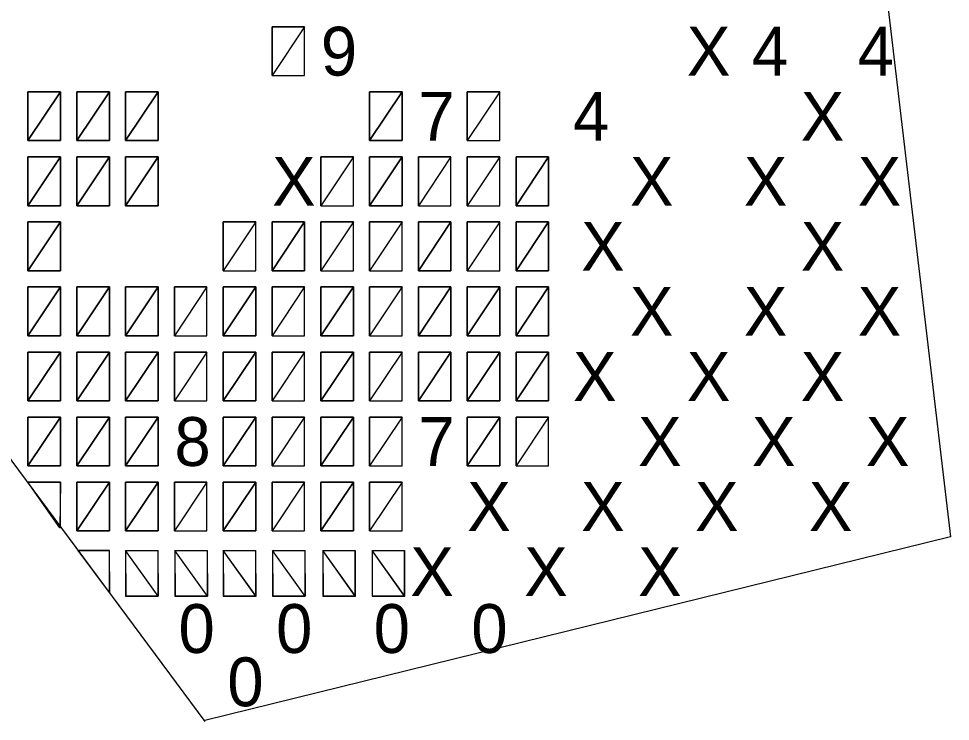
# Model space of a CAD drawing. Extents: x 0 to 44.3, y 0 to 22.
# Drawn here: x 4.6543 to 4.8173, y 1.2385 to 1.3615 of the extents above; entities that cross this region are included whole.
import ezdxf

# ---------------------------------------------------------------- set-up
doc = ezdxf.new("R2010")
doc.units = 0
doc.layers.add('Default', color=7, linetype='Continuous')

msp = doc.modelspace()

# ---------------------------------------------------------------- linework, layer by layer
at = {"layer": 'Default'}
for p, q in [((4.78805, 1.51939), (4.81727, 1.27081)), ((4.70432, 1.36004), (4.69863, 1.36004)), ((4.69863, 1.36004), (4.69863, 1.3515)), ((4.70432, 1.3515), (4.70432, 1.36004)), ((4.69863, 1.3515), (4.70432, 1.3515)), ((4.65595, 1.34866), (4.65595, 1.34012)), ((4.66164, 1.34866), (4.65595, 1.34866)), ((4.66164, 1.34012), (4.66164, 1.34866)), ((4.67018, 1.34866), (4.66449, 1.34866)), ((4.66449, 1.34866), (4.66449, 1.34012)), ((4.67018, 1.34012), (4.67018, 1.34866)), ((4.67302, 1.34866), (4.67302, 1.34012)), ((4.67871, 1.34866), (4.67302, 1.34866)), ((4.67871, 1.34012), (4.67871, 1.34866)), ((4.72139, 1.34866), (4.7157, 1.34866)), ((4.7157, 1.34866), (4.7157, 1.34012)), ((4.72139, 1.34012), (4.72139, 1.34866)), ((4.73277, 1.34866), (4.73277, 1.34012)), ((4.73846, 1.34866), (4.73277, 1.34866)), ((4.73846, 1.34012), (4.73846, 1.34866)), ((4.6068, 1.34644), (4.68687, 1.23853)), ((4.65595, 1.34012), (4.66164, 1.34012)), ((4.66449, 1.34012), (4.67018, 1.34012)), ((4.67302, 1.34012), (4.67871, 1.34012)), ((4.7157, 1.34012), (4.72139, 1.34012)), ((4.73277, 1.34012), (4.73846, 1.34012)), ((4.65595, 1.33728), (4.65595, 1.32874)), ((4.66164, 1.33728), (4.65595, 1.33728)), ((4.66164, 1.32874), (4.66164, 1.33728)), ((4.66449, 1.33728), (4.66449, 1.32874)), ((4.67018, 1.33728), (4.66449, 1.33728)), ((4.67018, 1.32874), (4.67018, 1.33728)), ((4.67871, 1.33728), (4.67302, 1.33728)), ((4.67302, 1.33728), (4.67302, 1.32874)), ((4.67871, 1.32874), (4.67871, 1.33728)), ((4.70717, 1.33728), (4.70717, 1.32874)), ((4.71286, 1.33728), (4.70717, 1.33728)), ((4.71286, 1.32874), (4.71286, 1.33728)), ((4.7157, 1.33728), (4.7157, 1.32874)), ((4.72139, 1.33728), (4.7157, 1.33728)), ((4.72139, 1.32874), (4.72139, 1.33728)), ((4.72993, 1.33728), (4.72424, 1.33728)), ((4.72424, 1.33728), (4.72424, 1.32874)), ((4.72993, 1.32874), (4.72993, 1.33728)), ((4.73846, 1.33728), (4.73277, 1.33728)), ((4.73277, 1.33728), (4.73277, 1.32874)), ((4.73846, 1.32874), (4.73846, 1.33728)), ((4.74131, 1.33728), (4.74131, 1.32874)), ((4.747, 1.33728), (4.74131, 1.33728)), ((4.747, 1.32874), (4.747, 1.33728)), ((4.65595, 1.32874), (4.66164, 1.32874)), ((4.66449, 1.32874), (4.67018, 1.32874)), ((4.67302, 1.32874), (4.67871, 1.32874)), ((4.70717, 1.32874), (4.71286, 1.32874)), ((4.7157, 1.32874), (4.72139, 1.32874)), ((4.72424, 1.32874), (4.72993, 1.32874)), ((4.73277, 1.32874), (4.73846, 1.32874)), ((4.74131, 1.32874), (4.747, 1.32874)), ((4.66164, 1.3259), (4.65595, 1.3259)), ((4.65595, 1.3259), (4.65595, 1.31736)), ((4.66164, 1.31736), (4.66164, 1.3259)), ((4.69578, 1.3259), (4.69009, 1.3259)), ((4.69009, 1.3259), (4.69009, 1.31736)), ((4.69578, 1.31736), (4.69578, 1.3259)), ((4.70432, 1.3259), (4.69863, 1.3259)), ((4.69863, 1.3259), (4.69863, 1.31736)), ((4.70432, 1.31736), (4.70432, 1.3259)), ((4.70717, 1.3259), (4.70717, 1.31736)), ((4.71286, 1.3259), (4.70717, 1.3259)), ((4.71286, 1.31736), (4.71286, 1.3259)), ((4.7157, 1.3259), (4.7157, 1.31736)), ((4.72139, 1.3259), (4.7157, 1.3259)), ((4.72139, 1.31736), (4.72139, 1.3259)), ((4.72424, 1.3259), (4.72424, 1.31736)), ((4.72993, 1.3259), (4.72424, 1.3259)), ((4.72993, 1.31736), (4.72993, 1.3259)), ((4.73846, 1.3259), (4.73277, 1.3259)), ((4.73277, 1.3259), (4.73277, 1.31736)), ((4.73846, 1.31736), (4.73846, 1.3259)), ((4.747, 1.3259), (4.74131, 1.3259)), ((4.74131, 1.3259), (4.74131, 1.31736)), ((4.747, 1.31736), (4.747, 1.3259)), ((4.65595, 1.31736), (4.66164, 1.31736)), ((4.69009, 1.31736), (4.69578, 1.31736)), ((4.69863, 1.31736), (4.70432, 1.31736)), ((4.70717, 1.31736), (4.71286, 1.31736)), ((4.7157, 1.31736), (4.72139, 1.31736)), ((4.72424, 1.31736), (4.72993, 1.31736)), ((4.73277, 1.31736), (4.73846, 1.31736)), ((4.74131, 1.31736), (4.747, 1.31736)), ((4.66164, 1.31452), (4.65595, 1.31452)), ((4.65595, 1.31452), (4.65595, 1.30598)), ((4.66164, 1.30598), (4.66164, 1.31452)), ((4.66449, 1.31452), (4.66449, 1.30598)), ((4.67018, 1.31452), (4.66449, 1.31452)), ((4.67018, 1.30598), (4.67018, 1.31452)), ((4.67871, 1.31452), (4.67302, 1.31452)), ((4.67302, 1.31452), (4.67302, 1.30598)), ((4.67871, 1.30598), (4.67871, 1.31452)), ((4.68156, 1.31452), (4.68156, 1.30598)), ((4.68725, 1.31452), (4.68156, 1.31452)), ((4.68725, 1.30598), (4.68725, 1.31452)), ((4.69578, 1.31452), (4.69009, 1.31452)), ((4.69009, 1.31452), (4.69009, 1.30598)), ((4.69578, 1.30598), (4.69578, 1.31452)), ((4.69863, 1.31452), (4.69863, 1.30598)), ((4.70432, 1.31452), (4.69863, 1.31452)), ((4.70432, 1.30598), (4.70432, 1.31452)), ((4.70717, 1.31452), (4.70717, 1.30598)), ((4.71286, 1.31452), (4.70717, 1.31452)), ((4.71286, 1.30598), (4.71286, 1.31452)), ((4.72139, 1.31452), (4.7157, 1.31452)), ((4.7157, 1.31452), (4.7157, 1.30598)), ((4.72139, 1.30598), (4.72139, 1.31452)), ((4.72993, 1.31452), (4.72424, 1.31452)), ((4.72424, 1.31452), (4.72424, 1.30598)), ((4.72993, 1.30598), (4.72993, 1.31452)), ((4.73277, 1.31452), (4.73277, 1.30598)), ((4.73846, 1.31452), (4.73277, 1.31452)), ((4.73846, 1.30598), (4.73846, 1.31452)), ((4.747, 1.31452), (4.74131, 1.31452)), ((4.74131, 1.31452), (4.74131, 1.30598)), ((4.747, 1.30598), (4.747, 1.31452)), ((4.65595, 1.30598), (4.66164, 1.30598)), ((4.66449, 1.30598), (4.67018, 1.30598)), ((4.67302, 1.30598), (4.67871, 1.30598)), ((4.68156, 1.30598), (4.68725, 1.30598)), ((4.69009, 1.30598), (4.69578, 1.30598)), ((4.69863, 1.30598), (4.70432, 1.30598)), ((4.70717, 1.30598), (4.71286, 1.30598)), ((4.7157, 1.30598), (4.72139, 1.30598)), ((4.72424, 1.30598), (4.72993, 1.30598)), ((4.73277, 1.30598), (4.73846, 1.30598)), ((4.74131, 1.30598), (4.747, 1.30598)), ((4.65595, 1.30314), (4.65595, 1.2946)), ((4.66164, 1.30314), (4.65595, 1.30314)), ((4.66164, 1.2946), (4.66164, 1.30314)), ((4.67018, 1.30314), (4.66449, 1.30314)), ((4.66449, 1.30314), (4.66449, 1.2946)), ((4.67018, 1.2946), (4.67018, 1.30314)), ((4.67302, 1.30314), (4.67302, 1.2946)), ((4.67871, 1.30314), (4.67302, 1.30314)), ((4.67871, 1.2946), (4.67871, 1.30314)), ((4.68725, 1.30314), (4.68156, 1.30314)), ((4.68156, 1.30314), (4.68156, 1.2946)), ((4.68725, 1.2946), (4.68725, 1.30314)), ((4.69009, 1.30314), (4.69009, 1.2946)), ((4.69578, 1.30314), (4.69009, 1.30314)), ((4.69578, 1.2946), (4.69578, 1.30314)), ((4.70432, 1.30314), (4.69863, 1.30314)), ((4.69863, 1.30314), (4.69863, 1.2946)), ((4.70432, 1.2946), (4.70432, 1.30314)), ((4.71286, 1.30314), (4.70717, 1.30314)), ((4.70717, 1.30314), (4.70717, 1.2946)), ((4.71286, 1.2946), (4.71286, 1.30314)), ((4.7157, 1.30314), (4.7157, 1.2946)), ((4.72139, 1.30314), (4.7157, 1.30314)), ((4.72139, 1.2946), (4.72139, 1.30314)), ((4.72424, 1.30314), (4.72424, 1.2946)), ((4.72993, 1.30314), (4.72424, 1.30314)), ((4.72993, 1.2946), (4.72993, 1.30314)), ((4.73846, 1.30314), (4.73277, 1.30314)), ((4.73277, 1.30314), (4.73277, 1.2946)), ((4.73846, 1.2946), (4.73846, 1.30314)), ((4.74131, 1.30314), (4.74131, 1.2946)), ((4.747, 1.30314), (4.74131, 1.30314)), ((4.747, 1.2946), (4.747, 1.30314)), ((4.65595, 1.2946), (4.66164, 1.2946)), ((4.66449, 1.2946), (4.67018, 1.2946)), ((4.67302, 1.2946), (4.67871, 1.2946)), ((4.68156, 1.2946), (4.68725, 1.2946)), ((4.69009, 1.2946), (4.69578, 1.2946)), ((4.69863, 1.2946), (4.70432, 1.2946)), ((4.70717, 1.2946), (4.71286, 1.2946)), ((4.7157, 1.2946), (4.72139, 1.2946)), ((4.72424, 1.2946), (4.72993, 1.2946)), ((4.73277, 1.2946), (4.73846, 1.2946)), ((4.74131, 1.2946), (4.747, 1.2946)), ((4.66164, 1.29176), (4.65595, 1.29176)), ((4.65595, 1.29176), (4.65595, 1.28322)), ((4.66164, 1.28322), (4.66164, 1.29176)), ((4.66449, 1.29176), (4.66449, 1.28322)), ((4.67018, 1.29176), (4.66449, 1.29176)), ((4.67018, 1.28322), (4.67018, 1.29176)), ((4.67871, 1.29176), (4.67302, 1.29176)), ((4.67302, 1.29176), (4.67302, 1.28322)), ((4.67871, 1.28322), (4.67871, 1.29176)), ((4.69578, 1.29176), (4.69009, 1.29176)), ((4.69009, 1.29176), (4.69009, 1.28322)), ((4.69578, 1.28322), (4.69578, 1.29176)), ((4.69863, 1.29176), (4.69863, 1.28322)), ((4.70432, 1.29176), (4.69863, 1.29176)), ((4.70432, 1.28322), (4.70432, 1.29176)), ((4.70717, 1.29176), (4.70717, 1.28322)), ((4.71286, 1.29176), (4.70717, 1.29176)), ((4.71286, 1.28322), (4.71286, 1.29176)), ((4.72139, 1.29176), (4.7157, 1.29176)), ((4.7157, 1.29176), (4.7157, 1.28322)), ((4.72139, 1.28322), (4.72139, 1.29176)), ((4.73846, 1.29176), (4.73277, 1.29176)), ((4.73277, 1.29176), (4.73277, 1.28322)), ((4.73846, 1.28322), (4.73846, 1.29176)), ((4.74131, 1.29176), (4.74131, 1.28322)), ((4.747, 1.29176), (4.74131, 1.29176)), ((4.747, 1.28322), (4.747, 1.29176)), ((4.65595, 1.28322), (4.66164, 1.28322)), ((4.66449, 1.28322), (4.67018, 1.28322)), ((4.67302, 1.28322), (4.67871, 1.28322)), ((4.69009, 1.28322), (4.69578, 1.28322)), ((4.69863, 1.28322), (4.70432, 1.28322)), ((4.70717, 1.28322), (4.71286, 1.28322)), ((4.7157, 1.28322), (4.72139, 1.28322)), ((4.73277, 1.28322), (4.73846, 1.28322)), ((4.74131, 1.28322), (4.747, 1.28322)), ((4.66164, 1.28038), (4.65595, 1.28038)), ((4.66164, 1.27232), (4.66164, 1.28038)), ((4.67018, 1.28038), (4.66449, 1.28038)), ((4.66449, 1.28038), (4.66449, 1.27184)), ((4.67018, 1.27184), (4.67018, 1.28038)), ((4.67302, 1.28038), (4.67302, 1.27184)), ((4.67871, 1.28038), (4.67302, 1.28038)), ((4.67871, 1.27184), (4.67871, 1.28038)), ((4.68725, 1.28038), (4.68156, 1.28038)), ((4.68156, 1.28038), (4.68156, 1.27184)), ((4.68725, 1.27184), (4.68725, 1.28038)), ((4.69009, 1.28038), (4.69009, 1.27184)), ((4.69578, 1.28038), (4.69009, 1.28038)), ((4.69578, 1.27184), (4.69578, 1.28038)), ((4.70432, 1.28038), (4.69863, 1.28038)), ((4.69863, 1.28038), (4.69863, 1.27184)), ((4.70432, 1.27184), (4.70432, 1.28038)), ((4.71286, 1.28038), (4.70717, 1.28038)), ((4.70717, 1.28038), (4.70717, 1.27184)), ((4.71286, 1.27184), (4.71286, 1.28038)), ((4.7157, 1.28038), (4.7157, 1.27184)), ((4.72139, 1.28038), (4.7157, 1.28038)), ((4.72139, 1.27184), (4.72139, 1.28038)), ((4.66449, 1.27184), (4.67018, 1.27184)), ((4.67302, 1.27184), (4.67871, 1.27184)), ((4.68156, 1.27184), (4.68725, 1.27184)), ((4.69009, 1.27184), (4.69578, 1.27184)), ((4.69863, 1.27184), (4.70432, 1.27184)), ((4.70717, 1.27184), (4.71286, 1.27184)), ((4.7157, 1.27184), (4.72139, 1.27184)), ((4.81727, 1.27081), (4.68686, 1.23868)), ((4.67019, 1.26841), (4.66475, 1.26841)), ((4.67018, 1.26101), (4.67018, 1.26841)), ((4.67302, 1.26841), (4.67302, 1.26046)), ((4.67303, 1.26841), (4.67871, 1.26841)), ((4.67871, 1.26046), (4.67871, 1.26841)), ((4.68164, 1.26841), (4.68164, 1.26046)), ((4.68165, 1.26841), (4.68733, 1.26841)), ((4.68733, 1.26046), (4.68733, 1.26841)), ((4.6901, 1.26841), (4.6901, 1.26046)), ((4.69011, 1.26841), (4.69579, 1.26841)), ((4.6958, 1.26046), (4.6958, 1.26841)), ((4.69873, 1.26841), (4.69873, 1.26046)), ((4.69873, 1.26841), (4.70441, 1.26841)), ((4.70442, 1.26046), (4.70442, 1.26841)), ((4.70751, 1.26841), (4.70751, 1.26046)), ((4.70751, 1.26841), (4.71319, 1.26841)), ((4.7132, 1.26046), (4.7132, 1.26841)), ((4.71613, 1.26841), (4.72181, 1.26841)), ((4.71613, 1.26841), (4.71613, 1.26046)), ((4.72182, 1.26046), (4.72182, 1.26841)), ((4.67302, 1.26046), (4.67871, 1.26046)), ((4.68164, 1.26046), (4.68733, 1.26046)), ((4.6901, 1.26046), (4.6958, 1.26046)), ((4.69873, 1.26046), (4.70442, 1.26046)), ((4.70751, 1.26046), (4.7132, 1.26046)), ((4.71613, 1.26046), (4.72182, 1.26046))]:
    msp.add_line(p, q, dxfattribs=at)
for points in [[(4.69863, 1.3515), (4.70432, 1.3515), (4.70432, 1.36004)], [(4.69863, 1.3515), (4.69863, 1.36004), (4.70432, 1.36004)], [(4.65595, 1.34012), (4.65595, 1.34866), (4.66164, 1.34866)], [(4.66164, 1.34866), (4.66164, 1.34012), (4.65595, 1.34012)], [(4.66164, 1.34866), (4.66164, 1.34866), (4.66164, 1.34866)], [(4.66449, 1.34012), (4.66449, 1.34866), (4.67018, 1.34866)], [(4.67018, 1.34866), (4.67018, 1.34012), (4.66449, 1.34012)], [(4.67871, 1.34866), (4.67871, 1.34012), (4.67302, 1.34012)], [(4.67302, 1.34012), (4.67302, 1.34866), (4.67871, 1.34866)], [(4.7157, 1.34012), (4.7157, 1.34866), (4.72139, 1.34866)], [(4.72139, 1.34866), (4.72139, 1.34012), (4.7157, 1.34012)], [(4.73277, 1.34012), (4.73277, 1.34866), (4.73846, 1.34866)], [(4.73277, 1.34012), (4.73846, 1.34012), (4.73846, 1.34866)], [(4.65595, 1.32874), (4.65595, 1.33728), (4.66164, 1.33728)], [(4.66164, 1.33728), (4.66164, 1.32874), (4.65595, 1.32874)], [(4.66164, 1.33728), (4.66164, 1.33728), (4.66164, 1.33728)], [(4.67018, 1.33728), (4.67018, 1.32874), (4.66449, 1.32874)], [(4.66449, 1.32874), (4.66449, 1.33728), (4.67018, 1.33728)], [(4.67302, 1.32874), (4.67302, 1.33728), (4.67871, 1.33728)], [(4.67871, 1.33728), (4.67871, 1.32874), (4.67302, 1.32874)], [(4.70717, 1.32874), (4.70717, 1.33728), (4.71286, 1.33728)], [(4.70717, 1.32874), (4.71286, 1.32874), (4.71286, 1.33728)], [(4.72139, 1.33728), (4.72139, 1.32874), (4.7157, 1.32874)], [(4.7157, 1.32874), (4.7157, 1.33728), (4.72139, 1.33728)], [(4.72424, 1.32874), (4.72993, 1.32874), (4.72993, 1.33728)], [(4.72424, 1.32874), (4.72424, 1.33728), (4.72993, 1.33728)], [(4.73277, 1.32874), (4.73846, 1.32874), (4.73846, 1.33728)], [(4.73277, 1.32874), (4.73277, 1.33728), (4.73846, 1.33728)], [(4.747, 1.33728), (4.747, 1.32874), (4.74131, 1.32874)], [(4.74131, 1.32874), (4.74131, 1.33728), (4.747, 1.33728)], [(4.66164, 1.3259), (4.66164, 1.31736), (4.65595, 1.31736)], [(4.65595, 1.31736), (4.65595, 1.3259), (4.66164, 1.3259)], [(4.66164, 1.3259), (4.66164, 1.3259), (4.66164, 1.3259)], [(4.69009, 1.31736), (4.69578, 1.31736), (4.69578, 1.3259)], [(4.69009, 1.31736), (4.69009, 1.3259), (4.69578, 1.3259)], [(4.69863, 1.31736), (4.69863, 1.3259), (4.70432, 1.3259)], [(4.70432, 1.3259), (4.70432, 1.31736), (4.69863, 1.31736)], [(4.70717, 1.31736), (4.70717, 1.3259), (4.71286, 1.3259)], [(4.70717, 1.31736), (4.71286, 1.31736), (4.71286, 1.3259)], [(4.7157, 1.31736), (4.7157, 1.3259), (4.72139, 1.3259)], [(4.7157, 1.31736), (4.72139, 1.31736), (4.72139, 1.3259)], [(4.72993, 1.3259), (4.72993, 1.31736), (4.72424, 1.31736)], [(4.72424, 1.31736), (4.72424, 1.3259), (4.72993, 1.3259)], [(4.73277, 1.31736), (4.73846, 1.31736), (4.73846, 1.3259)], [(4.73277, 1.31736), (4.73277, 1.3259), (4.73846, 1.3259)], [(4.74131, 1.31736), (4.74131, 1.3259), (4.747, 1.3259)], [(4.747, 1.3259), (4.747, 1.31736), (4.74131, 1.31736)], [(4.66164, 1.31452), (4.66164, 1.30598), (4.65595, 1.30598)], [(4.65595, 1.30598), (4.65595, 1.31452), (4.66164, 1.31452)], [(4.66164, 1.31452), (4.66164, 1.31452), (4.66164, 1.31452)], [(4.67018, 1.31452), (4.67018, 1.30598), (4.66449, 1.30598)], [(4.66449, 1.30598), (4.66449, 1.31452), (4.67018, 1.31452)], [(4.67302, 1.30598), (4.67302, 1.31452), (4.67871, 1.31452)], [(4.67871, 1.31452), (4.67871, 1.30598), (4.67302, 1.30598)], [(4.68156, 1.30598), (4.68156, 1.31452), (4.68725, 1.31452)], [(4.68156, 1.30598), (4.68725, 1.30598), (4.68725, 1.31452)], [(4.69009, 1.30598), (4.69009, 1.31452), (4.69578, 1.31452)], [(4.69578, 1.31452), (4.69578, 1.30598), (4.69009, 1.30598)], [(4.69863, 1.30598), (4.69863, 1.31452), (4.70432, 1.31452)], [(4.69863, 1.30598), (4.70432, 1.30598), (4.70432, 1.31452)], [(4.71286, 1.31452), (4.71286, 1.30598), (4.70717, 1.30598)], [(4.70717, 1.30598), (4.70717, 1.31452), (4.71286, 1.31452)], [(4.7157, 1.30598), (4.72139, 1.30598), (4.72139, 1.31452)], [(4.7157, 1.30598), (4.7157, 1.31452), (4.72139, 1.31452)], [(4.72993, 1.31452), (4.72993, 1.30598), (4.72424, 1.30598)], [(4.72424, 1.30598), (4.72424, 1.31452), (4.72993, 1.31452)], [(4.72993, 1.31452), (4.72993, 1.31452), (4.72993, 1.31452)], [(4.73277, 1.30598), (4.73277, 1.31452), (4.73846, 1.31452)], [(4.73846, 1.31452), (4.73846, 1.30598), (4.73277, 1.30598)], [(4.73846, 1.31452), (4.73846, 1.31452), (4.73846, 1.31452)], [(4.74131, 1.30598), (4.74131, 1.31452), (4.747, 1.31452)], [(4.747, 1.31452), (4.747, 1.30598), (4.74131, 1.30598)], [(4.65595, 1.2946), (4.65595, 1.30314), (4.66164, 1.30314)], [(4.66164, 1.30314), (4.66164, 1.2946), (4.65595, 1.2946)], [(4.66164, 1.30314), (4.66164, 1.30314), (4.66164, 1.30314)], [(4.66449, 1.2946), (4.66449, 1.30314), (4.67018, 1.30314)], [(4.67018, 1.30314), (4.67018, 1.2946), (4.66449, 1.2946)], [(4.67871, 1.30314), (4.67871, 1.2946), (4.67302, 1.2946)], [(4.67302, 1.2946), (4.67302, 1.30314), (4.67871, 1.30314)], [(4.68156, 1.2946), (4.68725, 1.2946), (4.68725, 1.30314)], [(4.68156, 1.2946), (4.68156, 1.30314), (4.68725, 1.30314)], [(4.69578, 1.30314), (4.69578, 1.2946), (4.69009, 1.2946)], [(4.69009, 1.2946), (4.69009, 1.30314), (4.69578, 1.30314)], [(4.69863, 1.2946), (4.70432, 1.2946), (4.70432, 1.30314)], [(4.69863, 1.2946), (4.69863, 1.30314), (4.70432, 1.30314)], [(4.70717, 1.2946), (4.70717, 1.30314), (4.71286, 1.30314)], [(4.71286, 1.30314), (4.71286, 1.2946), (4.70717, 1.2946)], [(4.7157, 1.2946), (4.7157, 1.30314), (4.72139, 1.30314)], [(4.7157, 1.2946), (4.72139, 1.2946), (4.72139, 1.30314)], [(4.72424, 1.2946), (4.72424, 1.30314), (4.72993, 1.30314)], [(4.72993, 1.30314), (4.72993, 1.2946), (4.72424, 1.2946)], [(4.72993, 1.30314), (4.72993, 1.30314), (4.72993, 1.30314)], [(4.73846, 1.30314), (4.73846, 1.2946), (4.73277, 1.2946)], [(4.73277, 1.2946), (4.73277, 1.30314), (4.73846, 1.30314)], [(4.73846, 1.30314), (4.73846, 1.30314), (4.73846, 1.30314)], [(4.747, 1.30314), (4.747, 1.2946), (4.74131, 1.2946)], [(4.74131, 1.2946), (4.74131, 1.30314), (4.747, 1.30314)], [(4.66164, 1.29176), (4.66164, 1.28322), (4.65595, 1.28322)], [(4.65595, 1.28322), (4.65595, 1.29176), (4.66164, 1.29176)], [(4.66164, 1.29176), (4.66164, 1.29176), (4.66164, 1.29176)], [(4.67018, 1.29176), (4.67018, 1.28322), (4.66449, 1.28322)], [(4.66449, 1.28322), (4.66449, 1.29176), (4.67018, 1.29176)], [(4.67302, 1.28322), (4.67302, 1.29176), (4.67871, 1.29176)], [(4.67871, 1.29176), (4.67871, 1.28322), (4.67302, 1.28322)], [(4.69009, 1.28322), (4.69009, 1.29176), (4.69578, 1.29176)], [(4.69578, 1.29176), (4.69578, 1.28322), (4.69009, 1.28322)], [(4.69863, 1.28322), (4.69863, 1.29176), (4.70432, 1.29176)], [(4.69863, 1.28322), (4.70432, 1.28322), (4.70432, 1.29176)], [(4.71286, 1.29176), (4.71286, 1.28322), (4.70717, 1.28322)], [(4.70717, 1.28322), (4.70717, 1.29176), (4.71286, 1.29176)], [(4.7157, 1.28322), (4.72139, 1.28322), (4.72139, 1.29176)], [(4.7157, 1.28322), (4.7157, 1.29176), (4.72139, 1.29176)], [(4.73277, 1.28322), (4.73277, 1.29176), (4.73846, 1.29176)], [(4.73846, 1.29176), (4.73846, 1.28322), (4.73277, 1.28322)], [(4.74131, 1.28322), (4.74131, 1.29176), (4.747, 1.29176)], [(4.74131, 1.28322), (4.747, 1.28322), (4.747, 1.29176)], [(4.66152, 1.27238), (4.65593, 1.2804), (4.66162, 1.2804)], [(4.66449, 1.27184), (4.66449, 1.28038), (4.67018, 1.28038)], [(4.67018, 1.28038), (4.67018, 1.27184), (4.66449, 1.27184)], [(4.67871, 1.28038), (4.67871, 1.27184), (4.67302, 1.27184)], [(4.67302, 1.27184), (4.67302, 1.28038), (4.67871, 1.28038)], [(4.68156, 1.27184), (4.68725, 1.27184), (4.68725, 1.28038)], [(4.68156, 1.27184), (4.68156, 1.28038), (4.68725, 1.28038)], [(4.69578, 1.28038), (4.69578, 1.27184), (4.69009, 1.27184)], [(4.69009, 1.27184), (4.69009, 1.28038), (4.69578, 1.28038)], [(4.69863, 1.27184), (4.70432, 1.27184), (4.70432, 1.28038)], [(4.69863, 1.27184), (4.69863, 1.28038), (4.70432, 1.28038)], [(4.70717, 1.27184), (4.70717, 1.28038), (4.71286, 1.28038)], [(4.71286, 1.28038), (4.71286, 1.27184), (4.70717, 1.27184)], [(4.7157, 1.27184), (4.7157, 1.28038), (4.72139, 1.28038)], [(4.7157, 1.27184), (4.72139, 1.27184), (4.72139, 1.28038)], [(4.66472, 1.26841), (4.67015, 1.26841), (4.67019, 1.26107)], [(4.67306, 1.26049), (4.67874, 1.26043), (4.67303, 1.26841)], [(4.67303, 1.26841), (4.67867, 1.26841), (4.67871, 1.26043)], [(4.68165, 1.26841), (4.68729, 1.26841), (4.68733, 1.26043)], [(4.68168, 1.26049), (4.68736, 1.26043), (4.68165, 1.26841)], [(4.69011, 1.26841), (4.69576, 1.26841), (4.69579, 1.26043)], [(4.69015, 1.26049), (4.69583, 1.26043), (4.69011, 1.26841)], [(4.69877, 1.26049), (4.70445, 1.26043), (4.69873, 1.26841)], [(4.69873, 1.26841), (4.70438, 1.26841), (4.70441, 1.26043)], [(4.70755, 1.26049), (4.71323, 1.26043), (4.70751, 1.26841)], [(4.70751, 1.26841), (4.71316, 1.26841), (4.71319, 1.26043)], [(4.71613, 1.26841), (4.72178, 1.26841), (4.72181, 1.26043)], [(4.71617, 1.26049), (4.72185, 1.26043), (4.71613, 1.26841)], [(4.67871, 1.26043), (4.67871, 1.26043), (4.67874, 1.26043), (4.67306, 1.26049)], [(4.68733, 1.26043), (4.68733, 1.26043), (4.68736, 1.26043), (4.68168, 1.26049)], [(4.69579, 1.26043), (4.69579, 1.26043), (4.69583, 1.26043), (4.69015, 1.26049)], [(4.70441, 1.26043), (4.70441, 1.26043), (4.70445, 1.26043), (4.69877, 1.26049)], [(4.71319, 1.26043), (4.71319, 1.26043), (4.71323, 1.26043), (4.70755, 1.26049)], [(4.72181, 1.26043), (4.72181, 1.26043), (4.72185, 1.26043), (4.71617, 1.26049)]]:
    msp.add_lwpolyline(points, close=True, dxfattribs=at)

# ---------------------------------------------------------------- texts
for s, p in [('9', (4.70717, 1.3515)), ('X', (4.77118, 1.3515)), ('4', (4.78256, 1.3515)), ('4', (4.80106, 1.3515)), ('7', (4.72424, 1.34012)), ('4', (4.75127, 1.34012)), ('X', (4.7911, 1.34012)), ('X', (4.69863, 1.32874)), ('X', (4.76122, 1.32874)), ('X', (4.78114, 1.32874)), ('X', (4.80106, 1.32874)), ('X', (4.75269, 1.31736)), ('X', (4.7911, 1.31736)), ('X', (4.76122, 1.30598)), ('X', (4.78114, 1.30598)), ('X', (4.80106, 1.30598)), ('X', (4.75127, 1.2946)), ('X', (4.77118, 1.2946)), ('X', (4.7911, 1.2946)), ('8', (4.68156, 1.28322)), ('7', (4.72424, 1.28322)), ('X', (4.76265, 1.28322)), ('X', (4.78256, 1.28322)), ('X', (4.80248, 1.28322)), ('X', (4.73277, 1.27184)), ('X', (4.75269, 1.27184)), ('X', (4.7726, 1.27184)), ('X', (4.79252, 1.27184)), ('X', (4.72281, 1.26046)), ('X', (4.74273, 1.26046)), ('X', (4.76265, 1.26046)), ('0', (4.68227, 1.2505)), ('0', (4.69934, 1.2505)), ('0', (4.71641, 1.2505)), ('0', (4.73348, 1.2505)), ('0', (4.69081, 1.24118))]:
    msp.add_text(s, height=0.00854, dxfattribs=at).set_placement(p)

doc.saveas('drawing.dxf')
